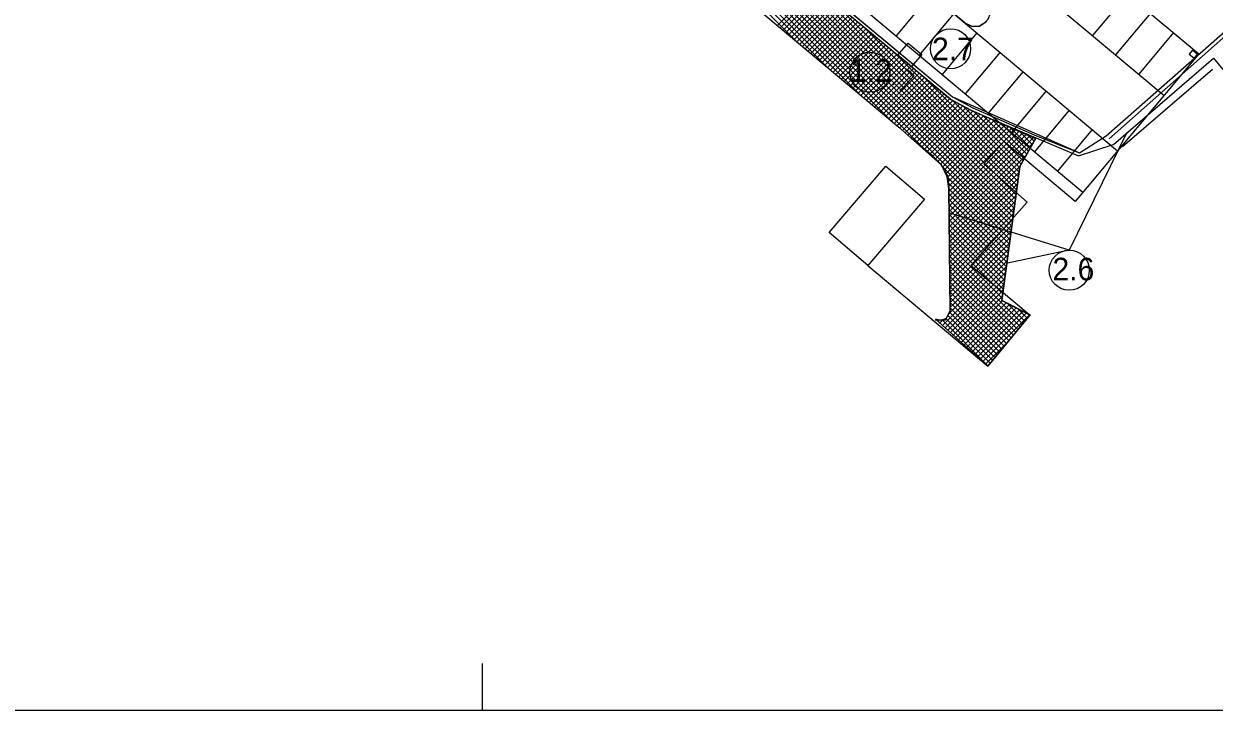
# Model space of a CAD drawing. Extents: x -438410 to -437811, y -1133174 to -1132817.
# Drawn here: x -438163.9 to -438065, y -1133049 to -1132992 of the extents above; entities that cross this region are included whole.
import ezdxf

# ---------------------------------------------------------------- set-up
doc = ezdxf.new("R2010")
doc.units = 0
for name, color, linetype in [('10 - legenda', 7, 'Continuous'), ('Vrstva 1', 7, 'Continuous'), ('Vrstva 5', 7, 'Continuous')]:
    doc.layers.add(name, color=color, linetype=linetype)

msp = doc.modelspace()

# ---------------------------------------------------------------- linework, layer by layer
at = {"layer": '10 - legenda'}
for p, q in [((-438130.345, -1132960.277), (-438081.816, -1133008.807)), ((-438130.201, -1132959.998), (-438081.765, -1133008.433)), ((-438130.49, -1132960.557), (-438081.866, -1133009.181)), ((-438114.348, -1132975.426), (-438081.715, -1133008.06)), ((-438111.867, -1132977.483), (-438081.664, -1133007.686)), ((-438109.386, -1132979.539), (-438081.613, -1133007.312)), ((-438106.906, -1132981.596), (-438081.563, -1133006.939)), ((-438104.37, -1132983.707), (-438081.512, -1133006.565)), ((-438101.822, -1132985.831), (-438081.462, -1133006.191)), ((-438099.275, -1132987.954), (-438081.411, -1133005.818)), ((-438101.282, -1132992.144), (-438098.084, -1132988.946)), ((-438101.051, -1132992.338), (-438097.853, -1132989.139)), ((-438101.676, -1132989.795), (-438088.496, -1133002.976)), ((-438100.82, -1132992.531), (-438097.621, -1132989.332)), ((-438100.589, -1132992.724), (-438097.39, -1132989.525)), ((-438100.358, -1132992.917), (-438097.159, -1132989.718)), ((-438100.127, -1132993.11), (-438096.927, -1132989.911)), ((-438099.895, -1132993.303), (-438096.696, -1132990.104)), ((-438096.727, -1132990.078), (-438081.361, -1133005.444)), ((-438102.207, -1132990.961), (-438099.712, -1132993.457)), ((-438102.014, -1132990.73), (-438097.132, -1132995.613)), ((-438101.821, -1132990.499), (-438094.552, -1132997.768)), ((-438101.628, -1132990.268), (-438091.972, -1132999.924)), ((-438099.664, -1132993.496), (-438096.464, -1132990.296)), ((-438099.433, -1132993.69), (-438096.233, -1132990.489)), ((-438099.202, -1132993.883), (-438096.002, -1132990.682)), ((-438098.971, -1132994.076), (-438095.77, -1132990.875)), ((-438098.74, -1132994.269), (-438095.539, -1132991.068)), ((-438098.509, -1132994.462), (-438095.307, -1132991.261)), ((-438098.277, -1132994.655), (-438095.076, -1132991.454)), ((-438098.046, -1132994.848), (-438094.845, -1132991.646)), ((-438097.815, -1132995.041), (-438094.613, -1132991.839)), ((-438097.584, -1132995.235), (-438094.382, -1132992.032)), ((-438097.353, -1132995.428), (-438094.15, -1132992.225)), ((-438097.122, -1132995.621), (-438093.919, -1132992.418)), ((-438096.891, -1132995.814), (-438093.688, -1132992.611)), ((-438096.66, -1132996.007), (-438093.456, -1132992.804)), ((-438096.428, -1132996.2), (-438093.225, -1132992.997)), ((-438094.179, -1132992.201), (-438081.31, -1133005.07)), ((-438096.197, -1132996.393), (-438092.993, -1132993.189)), ((-438095.966, -1132996.586), (-438092.762, -1132993.382)), ((-438095.735, -1132996.78), (-438092.531, -1132993.575)), ((-438095.504, -1132996.973), (-438092.299, -1132993.768)), ((-438095.273, -1132997.166), (-438092.068, -1132993.961)), ((-438095.042, -1132997.359), (-438091.836, -1132994.154)), ((-438094.81, -1132997.552), (-438091.605, -1132994.347)), ((-438094.579, -1132997.745), (-438091.374, -1132994.539)), ((-438094.348, -1132997.938), (-438091.142, -1132994.732)), ((-438094.117, -1132998.131), (-438090.911, -1132994.925)), ((-438091.632, -1132994.324), (-438081.259, -1133004.697)), ((-438093.886, -1132998.325), (-438090.679, -1132995.118)), ((-438093.655, -1132998.518), (-438090.448, -1132995.311)), ((-438093.424, -1132998.711), (-438090.217, -1132995.504)), ((-438093.192, -1132998.904), (-438089.985, -1132995.697)), ((-438092.961, -1132999.097), (-438089.754, -1132995.889)), ((-438092.73, -1132999.29), (-438089.522, -1132996.082)), ((-438092.499, -1132999.483), (-438089.291, -1132996.275)), ((-438092.268, -1132999.676), (-438089.06, -1132996.468)), ((-438092.037, -1132999.87), (-438088.828, -1132996.661)), ((-438091.806, -1133000.063), (-438088.597, -1132996.854)), ((-438091.575, -1133000.256), (-438088.365, -1132997.047)), ((-438089.084, -1132996.448), (-438081.209, -1133004.323)), ((-438091.343, -1133000.449), (-438088.134, -1132997.24)), ((-438091.114, -1133000.644), (-438087.903, -1132997.432)), ((-438090.89, -1133000.844), (-438087.671, -1132997.625)), ((-438090.666, -1133001.044), (-438087.44, -1132997.818)), ((-438090.441, -1133001.244), (-438087.208, -1132998.011)), ((-438090.217, -1133001.444), (-438086.977, -1132998.204)), ((-438089.992, -1133001.643), (-438086.719, -1132998.37)), ((-438089.768, -1133001.843), (-438086.442, -1132998.517)), ((-438089.543, -1133002.043), (-438086.165, -1132998.665)), ((-438089.319, -1133002.243), (-438085.888, -1132998.812)), ((-438089.094, -1133002.443), (-438085.611, -1132998.959)), ((-438086.759, -1132998.348), (-438081.158, -1133003.949)), ((-438085.852, -1132998.831), (-438081.036, -1133003.647)), ((-438088.87, -1133002.642), (-438085.334, -1132999.107)), ((-438088.646, -1133002.842), (-438085.051, -1132999.248)), ((-438088.421, -1133003.042), (-438084.757, -1132999.378)), ((-438088.197, -1133003.242), (-438084.462, -1132999.508)), ((-438087.972, -1133003.442), (-438084.168, -1132999.637)), ((-438087.748, -1133003.642), (-438083.873, -1132999.767)), ((-438087.579, -1133003.897), (-438083.579, -1132999.897)), ((-438087.422, -1133004.164), (-438083.285, -1133000.027)), ((-438084.979, -1132999.28), (-438080.884, -1133003.375)), ((-438084.22, -1132999.614), (-438080.731, -1133003.104)), ((-438083.461, -1132999.949), (-438080.578, -1133002.832)), ((-438087.264, -1133004.431), (-438082.99, -1133000.157)), ((-438087.118, -1133004.709), (-438082.696, -1133000.287)), ((-438087.092, -1133005.107), (-438082.401, -1133000.416)), ((-438087.065, -1133005.504), (-438082.107, -1133000.546)), ((-438087.051, -1133005.915), (-438081.812, -1133000.676)), ((-438087.046, -1133006.334), (-438081.518, -1133000.806)), ((-438087.04, -1133006.752), (-438081.224, -1133000.936)), ((-438082.703, -1133000.284), (-438080.425, -1133002.561)), ((-438081.944, -1133000.618), (-438080.272, -1133002.289)), ((-438081.185, -1133000.953), (-438080.12, -1133002.018)), ((-438087.035, -1133007.171), (-438080.929, -1133001.066)), ((-438087.03, -1133007.59), (-438080.635, -1133001.195)), ((-438087.024, -1133008.009), (-438080.34, -1133001.325)), ((-438087.019, -1133008.428), (-438080.046, -1133001.455)), ((-438087.014, -1133008.847), (-438080.036, -1133001.869)), ((-438080.426, -1133001.288), (-438079.967, -1133001.747)), ((-438087.008, -1133009.266), (-438080.582, -1133002.84)), ((-438087.587, -1133003.885), (-438081.917, -1133009.555)), ((-438087.003, -1133009.685), (-438081.129, -1133003.811)), ((-438087.113, -1133004.782), (-438081.967, -1133009.928)), ((-438086.998, -1133010.104), (-438081.208, -1133004.314)), ((-438086.992, -1133010.523), (-438081.274, -1133004.805)), ((-438087.083, -1133005.237), (-438082.018, -1133010.302)), ((-438087.054, -1133005.69), (-438082.069, -1133010.676)), ((-438086.987, -1133010.942), (-438081.34, -1133005.295)), ((-438086.982, -1133011.361), (-438081.407, -1133005.786)), ((-438087.048, -1133006.12), (-438082.119, -1133011.049)), ((-438087.043, -1133006.55), (-438082.17, -1133011.423)), ((-438086.976, -1133011.78), (-438081.473, -1133006.277)), ((-438086.971, -1133012.199), (-438081.54, -1133006.767)), ((-438087.037, -1133006.98), (-438082.22, -1133011.797)), ((-438087.032, -1133007.409), (-438082.271, -1133012.17)), ((-438087.026, -1133007.839), (-438082.321, -1133012.544)), ((-438086.966, -1133012.618), (-438081.606, -1133007.258)), ((-438086.96, -1133013.037), (-438081.672, -1133007.749)), ((-438087.021, -1133008.269), (-438082.372, -1133012.918)), ((-438087.015, -1133008.699), (-438082.423, -1133013.292)), ((-438086.955, -1133013.455), (-438081.739, -1133008.239)), ((-438086.95, -1133013.874), (-438081.805, -1133008.73)), ((-438087.01, -1133009.128), (-438082.473, -1133013.665)), ((-438087.005, -1133009.558), (-438082.524, -1133014.039)), ((-438086.944, -1133014.293), (-438081.872, -1133009.221)), ((-438086.939, -1133014.712), (-438081.938, -1133009.711)), ((-438086.999, -1133009.988), (-438082.574, -1133014.413)), ((-438086.994, -1133010.417), (-438082.625, -1133014.786)), ((-438086.988, -1133010.847), (-438080.92, -1133016.915)), ((-438086.934, -1133015.131), (-438082.004, -1133010.202)), ((-438086.928, -1133015.55), (-438082.071, -1133010.693)), ((-438087.571, -1133017.042), (-438082.204, -1133011.674)), ((-438087.099, -1133016.145), (-438082.137, -1133011.183)), ((-438086.983, -1133011.277), (-438081.112, -1133017.148)), ((-438086.977, -1133011.707), (-438081.304, -1133017.38)), ((-438087.348, -1133017.243), (-438082.27, -1133012.165)), ((-438087.125, -1133017.444), (-438082.336, -1133012.655)), ((-438086.972, -1133012.136), (-438081.495, -1133017.613)), ((-438086.966, -1133012.566), (-438081.687, -1133017.845)), ((-438086.961, -1133012.996), (-438081.879, -1133018.078)), ((-438086.955, -1133013.426), (-438082.071, -1133018.31)), ((-438086.95, -1133013.855), (-438082.262, -1133018.543)), ((-438086.902, -1133017.645), (-438082.403, -1133013.146)), ((-438086.678, -1133017.846), (-438082.469, -1133013.637)), ((-438086.944, -1133014.285), (-438082.454, -1133018.775)), ((-438086.939, -1133014.715), (-438082.646, -1133019.008)), ((-438086.455, -1133018.047), (-438082.536, -1133014.127)), ((-438086.232, -1133018.248), (-438082.602, -1133014.618)), ((-438086.934, -1133015.144), (-438082.838, -1133019.24)), ((-438086.928, -1133015.574), (-438083.029, -1133019.473)), ((-438086.009, -1133018.449), (-438082.577, -1133015.017)), ((-438085.785, -1133018.65), (-438082.294, -1133015.158)), ((-438085.562, -1133018.851), (-438082.011, -1133015.3)), ((-438085.339, -1133019.052), (-438081.728, -1133015.441)), ((-438085.116, -1133019.253), (-438081.445, -1133015.582)), ((-438084.892, -1133019.454), (-438081.162, -1133015.724)), ((-438084.669, -1133019.655), (-438080.879, -1133015.865)), ((-438082.212, -1133015.2), (-438080.728, -1133016.683)), ((-438081.364, -1133015.623), (-438080.537, -1133016.45)), ((-438088.084, -1133016.539), (-438087.68, -1133016.943)), ((-438088.018, -1133016.639), (-438087.952, -1133016.574)), ((-438087.794, -1133016.84), (-438087.514, -1133016.56)), ((-438087.604, -1133016.596), (-438083.796, -1133020.403)), ((-438087.299, -1133016.476), (-438083.605, -1133020.17)), ((-438087.136, -1133016.215), (-438083.413, -1133019.938)), ((-438086.989, -1133015.938), (-438083.221, -1133019.705)), ((-438084.446, -1133019.856), (-438080.596, -1133016.006)), ((-438084.223, -1133020.057), (-438080.314, -1133016.148)), ((-438080.516, -1133016.047), (-438080.345, -1133016.218)), ((-438084, -1133020.258), (-438082.159, -1133018.418))]:
    msp.add_line(p, q, dxfattribs=at)
for points in [[(-438155.418, -1132951.658), (-438154.459, -1132949.928), (-438152.986, -1132948.431), (-438150.952, -1132947.355), (-438149.044, -1132947.04), (-438145.423, -1132947.152), (-438140.626, -1132947.906), (-438137.256, -1132949.17), (-438134.381, -1132950.515), (-438131.551, -1132952.201), (-438128.583, -1132954.659), (-438124.25, -1132959.18), (-438121.599, -1132962.576), (-438119.849, -1132966.145), (-438117.528, -1132971.329), (-438116.418, -1132973.046), (-438114.656, -1132975.171), (-438090.957, -1132994.89), (-438086.882, -1132998.283), (-438085.153, -1132999.203), (-438076.272, -1133002.948), (-438073.404, -1133002.03)], [(-438073.738, -1133001.559), (-438034.962, -1132967.179), (-438033.461, -1132965.239), (-438031.779, -1132962.199), (-438030.513, -1132957.537), (-438030.279, -1132954.87), (-438030.35, -1132952.695)], [(-438106.298, -1132981.775), (-438086.742, -1132998.074), (-438076.181, -1133002.715), (-438073.986, -1133001.3), (-438047.351, -1132977.847)], [(-438102.409, -1132991.203), (-438091.189, -1133000.578), (-438087.711, -1133003.674), (-438087.12, -1133004.674), (-438087.054, -1133005.669), (-438086.925, -1133015.819), (-438087.269, -1133016.464), (-438087.71, -1133016.637), (-438088.147, -1133016.523), (-438083.814, -1133020.425), (-438080.295, -1133016.157), (-438082.651, -1133014.98), (-438081.143, -1133003.836), (-438079.851, -1133001.541), (-438085.153, -1132999.203), (-438086.882, -1132998.283), (-438106.458, -1132981.967)], [(-438106.298, -1132981.775), (-438090.797, -1132994.698), (-438086.742, -1132998.074), (-438085.044, -1132998.978), (-438079.755, -1133001.31), (-438076.181, -1133002.715)], [(-438083.899, -1132991.793), (-438084.499, -1132992.19), (-438085.111, -1132992.21), (-438085.689, -1132991.954)], [(-438073.373, -1133002.007), (-438065.053, -1132994.849), (-438064.278, -1132995.784)], [(-438088.189, -1133016.578), (-438087.33, -1133016.578), (-438086.925, -1133015.819), (-438086.925, -1133015.819), (-438087.054, -1133005.669), (-438087.191, -1133004.716), (-438087.665, -1133003.708), (-438088.396, -1133002.96), (-438090.146, -1133001.521)], [(-438079.851, -1133001.541), (-438081.143, -1133003.836), (-438082.651, -1133014.98), (-438080.281, -1133016.198)]]:
    msp.add_lwpolyline(points, dxfattribs=at)
msp.add_lwpolyline([(-438100.131, -1132976.753), (-438100.739, -1132976.454), (-438101.365, -1132976.522), (-438101.805, -1132976.809), (-438102.15, -1132977.319), (-438102.201, -1132977.897), (-438102.034, -1132978.315), (-438101.86, -1132978.557), (-438085.59, -1132991.987), (-438085.111, -1132992.21), (-438084.499, -1132992.19), (-438084.092, -1132991.916), (-438083.778, -1132991.611), (-438083.586, -1132991.118), (-438083.543, -1132990.748), (-438083.887, -1132990.058)], close=True, dxfattribs=at)
for centre in [(-438086.905, -1132994.067), (-438093.611, -1132996.019), (-438077.047, -1133012.462)]:
    msp.add_circle(centre, 1.666, dxfattribs=at)
at = {"layer": 'Vrstva 1'}
for p, q in [((-438091.577, -1132973.302), (-438066.281, -1132994.494)), ((-438094.467, -1132976.751), (-438069.171, -1132997.943)), ((-438098.32, -1132981.35), (-438073.024, -1133002.543)), ((-438101.21, -1132984.8), (-438075.914, -1133005.992)), ((-438088.546, -1132989.538), (-438091.436, -1132992.988)), ((-438072.221, -1132989.517), (-438075.111, -1132992.966)), ((-438086.63, -1132991.144), (-438089.52, -1132994.593)), ((-438070.305, -1132991.122), (-438073.195, -1132994.572)), ((-438084.714, -1132992.749), (-438087.603, -1132996.199)), ((-438068.389, -1132992.728), (-438071.279, -1132996.177)), ((-438082.797, -1132994.355), (-438085.687, -1132997.804)), ((-438066.287, -1132994.502), (-438076.556, -1133006.759)), ((-438080.881, -1132995.96), (-438083.771, -1132999.41)), ((-438078.964, -1132997.566), (-438081.854, -1133001.015)), ((-438077.048, -1132999.171), (-438079.938, -1133002.621)), ((-438075.132, -1133000.777), (-438078.022, -1133004.226)), ((-438093.782, -1133012.057), (-438083.814, -1133020.425)), ((-438080.295, -1133016.157), (-438083.82, -1133020.423)), ((-438125.824, -1133045.122), (-438125.824, -1133049.006)), ((-438230.824, -1133049.006), (-437810.824, -1133049.006))]:
    msp.add_line(p, q, dxfattribs=at)
for points in [[(-438066.775, -1132994.187), (-438066.402, -1132994.506), (-438066.7, -1132994.856), (-438067.074, -1132994.537)], [(-438092.275, -1133003.814), (-438089.073, -1133006.555), (-438093.782, -1133012.057), (-438096.995, -1133009.329)]]:
    msp.add_lwpolyline(points, close=True, dxfattribs=at)
msp.add_lwpolyline([(-438076.556, -1133006.759), (-438082.479, -1133001.777), (-438084.131, -1133003.626), (-438080.546, -1133006.803), (-438085.207, -1133012.071), (-438080.281, -1133016.198)], dxfattribs=at)
at = {"layer": 'Vrstva 5'}
for p, q in [((-438065.136, -1132995.789), (-438072.624, -1133002.216)), ((-438072.26, -1133001.029), (-438077.047, -1133010.796)), ((-438077.047, -1133010.796), (-438087.054, -1133007.699)), ((-438077.047, -1133010.796), (-438082.187, -1133011.864))]:
    msp.add_line(p, q, dxfattribs=at)
msp.add_lwpolyline([(-438091.273, -1132994.594), (-438090.421, -1132993.59), (-438089.295, -1132994.545), (-438090.147, -1132995.55)], close=True, dxfattribs=at)
msp.add_lwpolyline([(-438091.7, -1132997.072), (-438090.511, -1132995.775), (-438089.938, -1132996.3), (-438091.126, -1132997.598)], dxfattribs=at)

# ---------------------------------------------------------------- texts
for s, p in [('2.7', (-438088.445, -1132995.016)), ('1.2', (-438095.271, -1132996.817)), ('2.6', (-438078.444, -1133013.303))]:
    msp.add_text(s, height=1.875, dxfattribs=at).set_placement(p)

doc.saveas('drawing.dxf')
